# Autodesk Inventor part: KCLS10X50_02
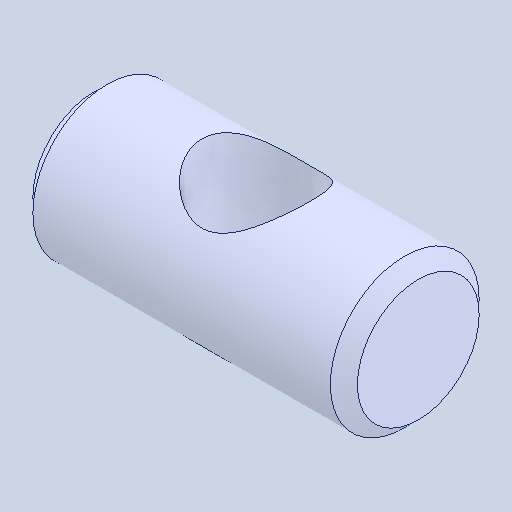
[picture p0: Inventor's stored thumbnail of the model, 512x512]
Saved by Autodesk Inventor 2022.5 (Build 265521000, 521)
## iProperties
Created: 2024-08
Part Number: KCLS10X50_02
Material: 一般
Document SubType Name: Modeling
Designer: ImaoCorp
Density: 1 g/cm^3
Appearance: 既定
Author: ImaoCorp
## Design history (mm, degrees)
feature "KCLS10X50_02"
node "ソリッド1"
